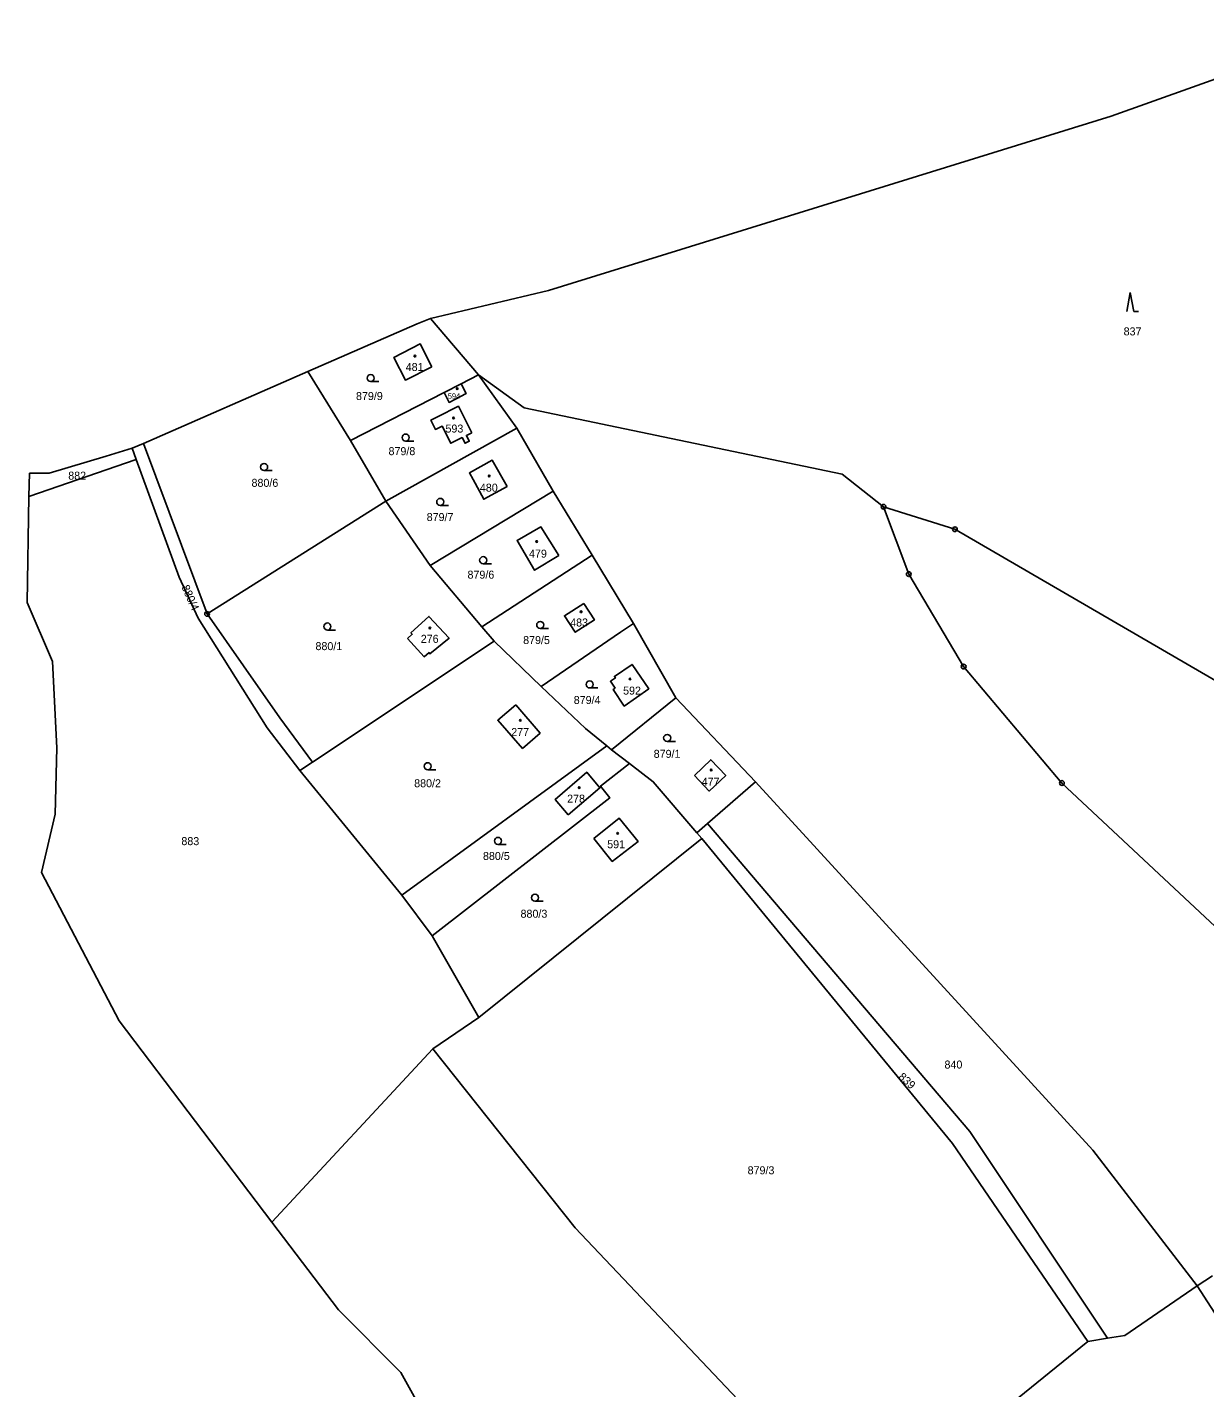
# Model space of a CAD drawing. Extents: x -725728 to -720881, y -1068679 to -1063504.
# Drawn here: x -723259.6 to -723009.4, y -1063934.3 to -1063645.3 of the extents above; entities that cross this region are included whole.
import ezdxf

# ---------------------------------------------------------------- set-up
doc = ezdxf.new("R2010")
doc.units = 0
for name, color, linetype in [('Hranice parcel', 7, 'Continuous'), ('Parcelní čísla', 7, 'Continuous'), ('Značky bodu BP', 7, 'Continuous'), ('Značky budov', 7, 'Continuous'), ('Značky kultur', 7, 'Continuous')]:
    doc.layers.add(name, color=color, linetype=linetype)

# ---------------------------------------------------------------- blocks, each defined once
blk = doc.blocks.new('4.02_3')
at = {"layer": 'Značky budov'}
blk.add_circle((-0.001, 0), 0.0175, dxfattribs=at)
blk = doc.blocks.new('4.02_4')
at = {"layer": 'Značky budov'}
blk.add_circle((-0.001, 0), 0.0175, dxfattribs=at)
blk = doc.blocks.new('3.04_2')
at = {"layer": 'Značky kultur'}
blk.add_line((0.001, 0), (0.176, 0), dxfattribs=at)
blk.add_circle((0.001, 0.075), 0.075, dxfattribs=at)
blk = doc.blocks.new('3.04_3')
at = {"layer": 'Značky kultur'}
blk.add_line((0.001, 0), (0.176, 0), dxfattribs=at)
blk.add_circle((0.001, 0.075), 0.075, dxfattribs=at)
blk = doc.blocks.new('3.08_2')
at = {"layer": 'Značky kultur'}
for p, q in [((0, 0.4), (-0.075, 0)), ((0.075, 0), (0, 0.4)), ((0.075, 0), (0.175, 0))]:
    blk.add_line(p, q, dxfattribs=at)
blk = doc.blocks.new('1.05_2')
at = {"layer": 'Značky bodu BP'}
for radius in [0.05, 0.00303]:
    blk.add_circle((0, 0), radius, dxfattribs=at)
blk = doc.blocks.new('1.05_1')
at = {"layer": 'Značky bodu BP'}
for radius in [0.05, 0.00303]:
    blk.add_circle((0, 0), radius, dxfattribs=at)

msp = doc.modelspace()

# ---------------------------------------------------------------- linework, layer by layer
at = {"layer": 'Hranice parcel'}
for p, q in [((-723029.31, -1063664.18), (-722976.49, -1063645.27)), ((-723199.96, -1063718.38), (-723176.73, -1063708.29)), ((-723176.73, -1063708.29), (-723173.93, -1063707.12)), ((-723173.93, -1063707.12), (-723163.7, -1063719.14)), ((-723234.89, -1063733.67), (-723199.96, -1063718.38)), ((-723199.96, -1063718.38), (-723190.92, -1063733.09)), ((-723171.01, -1063722.89), (-723167.41, -1063721.04)), ((-723163.7, -1063719.14), (-723167.41, -1063721.04)), ((-723163.7, -1063719.14), (-723155.54, -1063730.43)), ((-723171.01, -1063722.89), (-723190.92, -1063733.09)), ((-723155.54, -1063730.43), (-723183.38, -1063745.98)), ((-723155.54, -1063730.43), (-723147.83, -1063743.81)), ((-723242.84, -1063736.39), (-723237.31, -1063734.73)), ((-723237.31, -1063734.73), (-723234.89, -1063733.67)), ((-723237.31, -1063734.73), (-723236.45, -1063737.09)), ((-723221.38, -1063769.91), (-723234.89, -1063733.67)), ((-723190.92, -1063733.09), (-723183.38, -1063745.98)), ((-723259.21, -1063744.96), (-723236.45, -1063737.09)), ((-723259.21, -1063744.96), (-723259.13, -1063740)), ((-723147.83, -1063743.81), (-723173.98, -1063759.63)), ((-723147.83, -1063743.81), (-723139.56, -1063757.46)), ((-723183.38, -1063745.98), (-723221.38, -1063769.91)), ((-723183.38, -1063745.98), (-723173.98, -1063759.63)), ((-723139.56, -1063757.46), (-723163, -1063772.63)), ((-723139.56, -1063757.46), (-723130.79, -1063771.95)), ((-723173.98, -1063759.63), (-723163, -1063772.63)), ((-723163, -1063772.63), (-723160.39, -1063775.72)), ((-723130.79, -1063771.95), (-723121.78, -1063787.71)), ((-723199, -1063801.43), (-723160.39, -1063775.72)), ((-723160.39, -1063775.72), (-723150.39, -1063785.32)), ((-723121.78, -1063787.71), (-723135.42, -1063798.75)), ((-723121.78, -1063787.71), (-723104.87, -1063805.58)), ((-723179.96, -1063829.63), (-723136.44, -1063797.96)), ((-723136.44, -1063797.96), (-723135.42, -1063798.75)), ((-723135.42, -1063798.75), (-723131.62, -1063801.66)), ((-723199, -1063801.43), (-723201.64, -1063803.19)), ((-723201.64, -1063803.19), (-723179.96, -1063829.63)), ((-723115.03, -1063814.45), (-723104.87, -1063805.58)), ((-723117.31, -1063816.44), (-723115.03, -1063814.45)), ((-723116.28, -1063817.65), (-723117.31, -1063816.44)), ((-723116.28, -1063817.65), (-723163.65, -1063855.65)), ((-723179.96, -1063829.63), (-723173.52, -1063838.3)), ((-723173.52, -1063838.3), (-723163.65, -1063855.65)), ((-723163.65, -1063855.65), (-723173.42, -1063862.32)), ((-723207.59, -1063899.11), (-723173.42, -1063862.32)), ((-723011.01, -1063912.67), (-723007.76, -1063910.49)), ((-723011.01, -1063912.67), (-722968.06, -1063979.33)), ((-723082.94, -1063963.85), (-723034.21, -1063924.45)), ((-723034.21, -1063924.45), (-723030.08, -1063923.78))]:
    msp.add_line(p, q, dxfattribs=at)
for points in [[(-723173.93, -1063707.12), (-723148.81, -1063701.19), (-723029.31, -1063664.18)], [(-723173.59, -1063717.39), (-723179.24, -1063720.22), (-723181.71, -1063715.46), (-723176.08, -1063712.54), (-723173.59, -1063717.39)], [(-723167.41, -1063721.04), (-723166.35, -1063723.11), (-723169.95, -1063724.96), (-723171.01, -1063722.89)], [(-723163.7, -1063719.14), (-723153.98, -1063726.1), (-723086.43, -1063740.21), (-723077.65, -1063747.13)], [(-723165.11, -1063731.41), (-723166.28, -1063731.99), (-723165.67, -1063733.21), (-723166.57, -1063733.66), (-723167.18, -1063732.44), (-723169.6, -1063733.66), (-723171.44, -1063730), (-723172.84, -1063730.7), (-723173.83, -1063728.72), (-723172.43, -1063728.02), (-723167.97, -1063725.78), (-723165.11, -1063731.41)], [(-723259.13, -1063740), (-723254.91, -1063740.01), (-723242.84, -1063736.39)], [(-723236.45, -1063737.09), (-723227.33, -1063762.11), (-723223.25, -1063770.81), (-723208.63, -1063794.09), (-723201.64, -1063803.19)], [(-723157.63, -1063742.84), (-723162.57, -1063745.55), (-723164.86, -1063741.38), (-723165.64, -1063739.96), (-723160.77, -1063737.28), (-723157.63, -1063742.84)], [(-723256.56, -1063824.81), (-723253.63, -1063812.43), (-723253.26, -1063798.36), (-723254.23, -1063780.05), (-723259.59, -1063767.51), (-723259.21, -1063744.96)], [(-723077.65, -1063747.13), (-723072.29, -1063761.46), (-723060.62, -1063781.08), (-723039.73, -1063805.83), (-722984.36, -1063857.65)], [(-722990, -1063794.02), (-723062.47, -1063751.93), (-723077.65, -1063747.13)], [(-723146.65, -1063757.48), (-723151.8, -1063760.64), (-723155.49, -1063754.31), (-723150.45, -1063751.42), (-723146.65, -1063757.48)], [(-723221.38, -1063769.91), (-723205.93, -1063791.95), (-723199, -1063801.43)], [(-723141.33, -1063767.66), (-723139.07, -1063771.18), (-723143.16, -1063773.81), (-723145.43, -1063770.3), (-723141.33, -1063767.66)], [(-723178.76, -1063775.12), (-723177.77, -1063774.23), (-723178.05, -1063773.93), (-723174.24, -1063770.43), (-723169.97, -1063775.08), (-723174.01, -1063778.4), (-723174.2, -1063778.12), (-723175.27, -1063778.99), (-723178.76, -1063775.12)], [(-723130.79, -1063771.95), (-723133.55, -1063773.76), (-723150.39, -1063785.32)], [(-723134.66, -1063785.68), (-723135.66, -1063784.22), (-723134.62, -1063783.51), (-723134.84, -1063783.19), (-723131.08, -1063780.62), (-723127.53, -1063785.81), (-723132.72, -1063789.47), (-723135.1, -1063785.98), (-723134.66, -1063785.68)], [(-723150.39, -1063785.32), (-723140.98, -1063794.28), (-723136.44, -1063797.96)], [(-723155.74, -1063789.19), (-723150.61, -1063795.21), (-723154.35, -1063798.49), (-723159.6, -1063792.48), (-723155.74, -1063789.19)], [(-723131.62, -1063801.66), (-723137.77, -1063806.48), (-723135.82, -1063808.99), (-723173.52, -1063838.3)], [(-723131.62, -1063801.66), (-723126.57, -1063805.55), (-723117.31, -1063816.44)], [(-723117.84, -1063804.25), (-723114.37, -1063800.87), (-723111.17, -1063804.24), (-723114.67, -1063807.56), (-723117.84, -1063804.25)], [(-723144.68, -1063812.59), (-723147.42, -1063809.36), (-723140.7, -1063803.56), (-723137.9, -1063806.88), (-723144.68, -1063812.59)], [(-723104.87, -1063805.58), (-723033.15, -1063883.82), (-723011.01, -1063912.67)], [(-723139.17, -1063817.61), (-723133.78, -1063813.3), (-723129.81, -1063818.25), (-723135.27, -1063822.47), (-723139.17, -1063817.61)], [(-723030.08, -1063923.78), (-723059.34, -1063879.89), (-723115.03, -1063814.45)], [(-723034.21, -1063924.45), (-723062.96, -1063882.4), (-723116.28, -1063817.65)], [(-723207.59, -1063899.11), (-723240.02, -1063856.36), (-723256.56, -1063824.81)], [(-723173.42, -1063862.32), (-723143.13, -1063900.35), (-723082.94, -1063963.85)], [(-723177.02, -1063936.78), (-723180.17, -1063931.07), (-723193.45, -1063917.76), (-723207.59, -1063899.11)], [(-723030.08, -1063923.78), (-723026.36, -1063923.18), (-723011.01, -1063912.67)]]:
    msp.add_lwpolyline(points, dxfattribs=at)

# ---------------------------------------------------------------- block references
at = {"layer": 'Značky bodu BP', "xscale": 10, "yscale": 10}
for name, p in [('1.05_2', (-723077.65, -1063747.13)), ('1.05_2', (-723062.47, -1063751.93)), ('1.05_1', (-723072.29, -1063761.46)), ('1.05_2', (-723221.38, -1063769.91)), ('1.05_1', (-723060.62, -1063781.08)), ('1.05_1', (-723039.73, -1063805.83))]:
    msp.add_blockref(name, p, dxfattribs=at)
at = {"layer": 'Značky budov', "xscale": 10, "yscale": 10}
for name, p in [('4.02_4', (-723177.21, -1063715.14)), ('4.02_3', (-723168.22, -1063722.05)), ('4.02_3', (-723168.99, -1063728.28)), ('4.02_3', (-723161.41, -1063740.62)), ('4.02_3', (-723151.34, -1063754.54)), ('4.02_3', (-723141.89, -1063769.46)), ('4.02_4', (-723174.03, -1063772.9)), ('4.02_3', (-723131.52, -1063783.72)), ('4.02_3', (-723154.81, -1063792.5)), ('4.02_3', (-723114.24, -1063803.05)), ('4.02_3', (-723142.29, -1063806.8)), ('4.02_3', (-723134.14, -1063816.51))]:
    msp.add_blockref(name, p, dxfattribs=at)
at = {"layer": 'Značky kultur', "xscale": 10, "yscale": 10}
for name, p in [('3.08_2', (-723025.23, -1063705.66)), ('3.04_2', (-723186.62, -1063720.55)), ('3.04_2', (-723179.19, -1063733.19)), ('3.04_2', (-723209.27, -1063739.45)), ('3.04_2', (-723171.85, -1063746.86)), ('3.04_2', (-723162.72, -1063759.24)), ('3.04_2', (-723195.82, -1063773.33)), ('3.04_2', (-723150.6, -1063773)), ('3.04_3', (-723140.1, -1063785.64)), ('3.04_2', (-723123.62, -1063797)), ('3.04_2', (-723174.5, -1063803.01)), ('3.04_2', (-723159.57, -1063818.87)), ('3.04_2', (-723151.7, -1063830.94))]:
    msp.add_blockref(name, p, dxfattribs=at)

# ---------------------------------------------------------------- texts
at = {"layer": 'Parcelní čísla'}
for s, height, p in [('837', 1.7, (-723026.63, -1063710.74)), ('481', 1.7, (-723179.17, -1063718.31)), ('879/9', 1.7, (-723189.73, -1063724.47)), ('594', 1.14, (-723170.23, -1063724.2)), ('593', 1.7, (-723170.72, -1063731.38)), ('879/8', 1.7, (-723182.82, -1063736.18)), ('882', 1.7, (-723250.87, -1063741.38)), ('880/6', 1.7, (-723211.93, -1063742.91)), ('480', 1.7, (-723163.41, -1063743.94)), ('879/7', 1.7, (-723174.71, -1063750.18)), ('479', 1.7, (-723152.97, -1063757.95)), ('879/6', 1.7, (-723166.04, -1063762.42)), ('483', 1.7, (-723144.23, -1063772.58)), ('880/1', 1.7, (-723198.34, -1063777.6)), ('276', 1.7, (-723175.97, -1063776.05)), ('879/5', 1.7, (-723154.22, -1063776.31)), ('879/4', 1.7, (-723143.47, -1063789.04)), ('592', 1.7, (-723132.98, -1063787.05)), ('277', 1.7, (-723156.75, -1063795.85)), ('879/1', 1.7, (-723126.48, -1063800.48)), ('477', 1.7, (-723116.28, -1063806.39)), ('880/2', 1.7, (-723177.37, -1063806.73)), ('278', 1.7, (-723144.87, -1063810)), ('883', 1.7, (-723226.83, -1063819.03)), ('591', 1.7, (-723136.36, -1063819.69)), ('880/5', 1.7, (-723162.75, -1063822.18)), ('880/3', 1.7, (-723154.77, -1063834.45)), ('840', 1.7, (-723064.69, -1063866.49)), ('879/3', 1.7, (-723106.52, -1063888.95))]:
    msp.add_text(s, height=height, dxfattribs=at).set_placement(p)
for s, rotation, p in [('880/4', 294, (-723226.85, -1063764.2)), ('839', 318, (-723074.63, -1063868.45))]:
    msp.add_text(s, height=1.7, rotation=rotation, dxfattribs=at).set_placement(p)

doc.saveas('drawing.dxf')
